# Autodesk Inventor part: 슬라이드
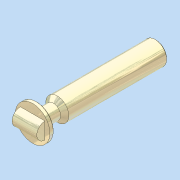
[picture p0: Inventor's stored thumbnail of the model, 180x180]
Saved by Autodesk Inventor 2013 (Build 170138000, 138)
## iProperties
Company: 한국ATC센터
Created: 2014-10
Part Number: 슬라이드
Document SubType Name: Modeling
Designer: 한국ATC센터
Density: 7.86 g/cm^3
Material: 강철, 연강
Mass: 728.405 g
Surface Area: 164.68 cm^2
Volume: 92.6724 cm^3
Author: KYOUNG IL JANG
Revision Number: 1
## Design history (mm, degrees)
sketch "스케치1"
  geometry: L1 (-14, 195)-(-14, 171) reference; L2 (19, 106.5)-(-19, 106.5) reference; L3 (0, 106.5)-(0, 256.5); L4 (0, 256.5)-(-14, 256.5); L5 (-14, 256.5)-(-14, 136.5); L6 (-14, 111.5)-(-21, 111.5); L7 (-21, 111.5)-(-21, 106.5); L8 (-21, 106.5)-(0, 106.5); L9 (-14, 111.5)-(-9, 111.5); L10 (-9, 111.5)-(-9, 131.5); L11 (-9, 131.5)-(-14, 136.5); L12 (-14, 136.5)-(-14, 111.5); 1 further point
  constraints: 24 end point, 5 perpendicular, 3 parallel, 1 collinear, 1 horizontal, 1 midpoint, 1 point on line, 1 vertical, 4 other
  dimensions: "d0" = 5 distance between parallel lines of L6 L8; "d1" = 42 diameter of L7 L3; "d2" = 150 distance of L3.start L3.end; "d3" = 135 deg angle of L11 L5; "d4" = 18 diameter of L10 L3; "d5" = 30 distance from line of L5.end L8
revolve "회전1" sketch "스케치1" stored, may be unused: angle "d6" = 90 deg
chamfer "모따기1" distance "d7" = 1; stored, may be unused: second distance "d8" = 2, angle "d9" = 45 deg
fillet "모깎기1" dims "d10" = 2
sketch "스케치2"
  geometry: L1 (21, 106.5)-(-21, 106.5) reference; L2 (-15, 96.5)-(15, 96.5); L3 (15, 96.5)-(15, 106.5); L4 (15, 106.5)-(-15, 106.5); L5 (-15, 106.5)-(-15, 96.5); 2 further points
  constraints: 8 end point, 2 midpoint, 2 parallel, 1 horizontal, 1 perpendicular, 1 point on line
  dimensions: "d11" = 20 diameter of L2 L4; "d12" = 30 distance between parallel lines of L3 L5
revolve "회전2" sketch "스케치2" stored, may be unused: angle "d13" = 180 deg
node "솔리드1"
